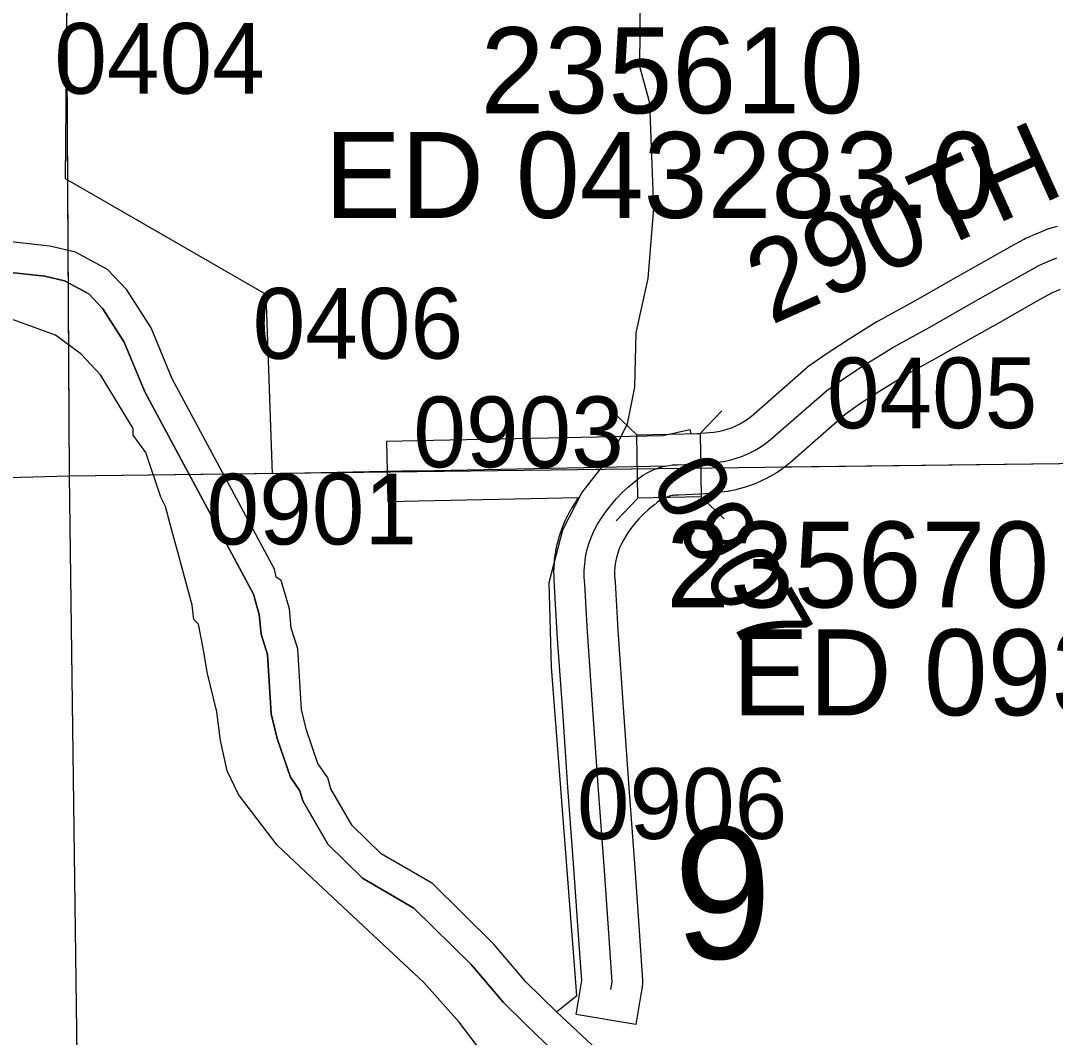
# Model space of a CAD drawing. Extents: x 23.6 to 68.7, y -63 to -29.
# Drawn here: x 40.707 to 41.731, y -53.223 to -52.217 of the extents above; entities that cross this region are included whole.
import ezdxf

# ---------------------------------------------------------------- set-up
doc = ezdxf.new("R2010")
doc.units = 0
for name, color, linetype in [('tdCoHydroRiver', 7, 'Continuous'), ('tdCoSecRdNmbr', 7, 'Continuous'), ('tdCoSecRdTxt', 7, 'Continuous'), ('tdCoSecRteBand', 7, 'Continuous'), ('tdCoSecRteCL', 7, 'Continuous'), ('tdCoSectLine', 7, 'Continuous'), ('tdCoSectLinePart', 7, 'Continuous'), ('tdCoSectNmbr', 7, 'Continuous'), ('tdCoStrucSec', 7, 'Continuous'), ('tdCoStrucSecCoName', 7, 'Continuous'), ('tdCoStrucSecFHWANum', 7, 'Continuous'), ('tdCoSurfEarth', 7, 'Continuous'), ('tdCoSurfGravel', 7, 'Continuous'), ('tdCoSurfLNO', 7, 'Continuous'), ('tdCoTwpBndry', 7, 'Continuous'), ('tdCoTwpBndryShd', 7, 'Continuous')]:
    doc.layers.add(name, color=color, linetype=linetype)

msp = doc.modelspace()

# ---------------------------------------------------------------- linework, layer by layer
at = {"layer": 'tdCoHydroRiver'}
for points in [[(41.2371, -53.1973), (41.2575, -53.1813), (41.2323, -52.8564), (41.2299, -52.7727), (41.2436, -52.7205), (41.2622, -52.684), (41.2919, -52.6458), (41.3074, -52.6157), (41.3149, -52.5793), (41.316, -52.5256), (41.3281, -52.4718), (41.3337, -52.4023), (41.3296, -52.2982), (41.3198, -52.262), (41.3222, -52.0157)], [(41.2371, -53.1973), (41.2068, -53.1676), (41.1749, -53.13), (41.1144, -53.0706), (41.0636, -53.0411), (41.0349, -53.0129), (41.014, -52.9768), (41.0108, -52.9658), (41.0011, -52.9517), (40.9898, -52.9186), (40.9849, -52.8982), (40.9811, -52.8382), (40.9746, -52.8178), (40.9729, -52.7988), (40.9647, -52.7705), (40.9599, -52.7674), (40.9583, -52.7595), (40.857, -52.571), (40.836, -52.5207), (40.812, -52.4831), (40.7929, -52.4627), (40.7611, -52.4457), (40.7358, -52.4396), (40.6821, -52.4338)], [(41.1921, -53.2751), (41.1409, -53.2077), (41.1058, -53.1685), (41.0007, -53.0701), (40.9609, -53.0326), (40.9225, -52.9824), (40.9112, -52.9589), (40.9046, -52.9289), (40.9012, -52.9005), (40.8914, -52.8612), (40.888, -52.8391), (40.883, -52.8139), (40.8782, -52.8092), (40.8765, -52.795), (40.8634, -52.7462), (40.8553, -52.7163), (40.8504, -52.6974), (40.8455, -52.688), (40.8309, -52.6439), (40.8181, -52.6267), (40.8181, -52.6203), (40.786, -52.567), (40.7668, -52.5466), (40.7414, -52.5279), (40.6907, -52.5095)], [(41.7341, -53.6693), (41.7276, -53.6551), (41.7117, -53.6427), (41.6468, -53.6149), (41.5896, -53.5807), (41.5466, -53.5385), (41.5481, -53.5306), (41.5322, -53.5165), (41.505, -53.4836), (41.4812, -53.4649), (41.462, -53.4382), (41.4284, -53.3944), (41.3072, -53.2629), (41.2371, -53.1973)]]:
    msp.add_lwpolyline(points, dxfattribs=at)
at = {"layer": 'tdCoSecRteBand'}
msp.add_lwpolyline([(41.7356, -52.4826), (41.7277, -52.486), (41.7156, -52.4926), (41.669, -52.5191), (41.6689, -52.5191), (41.6689, -52.5191), (41.6213, -52.546), (41.6212, -52.5461), (41.621, -52.5462), (41.5855, -52.5658), (41.5563, -52.584), (41.5383, -52.5956), (41.5231, -52.6064), (41.469, -52.6537), (41.4683, -52.6543), (41.4677, -52.6548), (41.4625, -52.6588), (41.4617, -52.6594), (41.4609, -52.66), (41.4555, -52.6636), (41.4547, -52.6642), (41.4539, -52.6647), (41.4482, -52.668), (41.4474, -52.6685), (41.4465, -52.6689), (41.4407, -52.6718), (41.4398, -52.6723), (41.4389, -52.6727), (41.4329, -52.6752), (41.432, -52.6756), (41.431, -52.6759), (41.4249, -52.678), (41.4239, -52.6783), (41.423, -52.6786), (41.4167, -52.6803), (41.4158, -52.6806), (41.4148, -52.6808), (41.4084, -52.6821), (41.4074, -52.6823), (41.4065, -52.6824), (41.4, -52.6833), (41.3994, -52.6834), (41.3989, -52.6834), (41.3811, -52.6852), (41.3802, -52.6852), (41.3792, -52.6853), (41.3581, -52.686), (41.3545, -52.6862), (41.353, -52.6864), (41.3518, -52.6866), (41.3491, -52.6872), (41.3464, -52.688), (41.3439, -52.689), (41.3414, -52.6903), (41.339, -52.6917), (41.3368, -52.6933), (41.3338, -52.6959), (41.3336, -52.696), (41.3335, -52.6962), (41.328, -52.7007), (41.3233, -52.705), (41.3189, -52.7096), (41.3147, -52.7143), (41.3108, -52.7193), (41.3072, -52.7245), (41.3039, -52.7299), (41.3011, -52.735), (41.2994, -52.739), (41.2979, -52.7434), (41.2966, -52.7479), (41.2957, -52.7524), (41.295, -52.757), (41.2947, -52.7617), (41.2948, -52.7663), (41.2952, -52.772), (41.2952, -52.7722), (41.2952, -52.7724), (41.2979, -52.8196), (41.3036, -52.9008), (41.3085, -52.9713), (41.3147, -53.0553), (41.3147, -53.0554), (41.3147, -53.0554), (41.3193, -53.122), (41.3193, -53.122), (41.3193, -53.1221), (41.3223, -53.166), (41.3225, -53.1695), (41.322, -53.1729), (41.3207, -53.1803), (41.3158, -53.2099), (41.2566, -53.2), (41.2616, -53.1705), (41.2622, -53.1665), (41.2595, -53.1262), (41.2548, -53.0597), (41.2486, -52.9756), (41.2486, -52.9756), (41.2486, -52.9755), (41.2437, -52.905), (41.2437, -52.905), (41.2437, -52.905), (41.238, -52.8236), (41.238, -52.8234), (41.238, -52.8232), (41.2353, -52.7761), (41.2348, -52.7696), (41.2348, -52.7686), (41.2348, -52.7676), (41.2347, -52.7609), (41.2347, -52.7598), (41.2348, -52.7588), (41.2352, -52.7521), (41.2353, -52.7511), (41.2354, -52.7501), (41.2363, -52.7434), (41.2365, -52.7424), (41.2367, -52.7414), (41.238, -52.7348), (41.2382, -52.7338), (41.2385, -52.7328), (41.2403, -52.7263), (41.2406, -52.7253), (41.2409, -52.7244), (41.2432, -52.718), (41.2435, -52.7171), (41.2439, -52.7161), (41.2466, -52.71), (41.2471, -52.7087), (41.2478, -52.7075), (41.2516, -52.7005), (41.252, -52.6998), (41.2524, -52.6991), (41.2566, -52.6923), (41.257, -52.6917), (41.2575, -52.691), (41.259, -52.6889), (41.1006, -52.6921), (41.0706, -52.6927), (41.0694, -52.6327), (41.0994, -52.6321), (41.3428, -52.6271), (41.3692, -52.6212), (41.3701, -52.6256), (41.3762, -52.6253), (41.3925, -52.6238), (41.3974, -52.6231), (41.4018, -52.6222), (41.4062, -52.621), (41.4105, -52.6195), (41.4147, -52.6177), (41.4187, -52.6157), (41.4227, -52.6134), (41.4264, -52.6109), (41.4301, -52.608), (41.4847, -52.5602), (41.4858, -52.5592), (41.4871, -52.5583), (41.5041, -52.5462), (41.5047, -52.5459), (41.5052, -52.5455), (41.524, -52.5334), (41.5242, -52.5333), (41.5244, -52.5332), (41.5544, -52.5144), (41.5551, -52.514), (41.5558, -52.5136), (41.5919, -52.4937), (41.6394, -52.4669), (41.6862, -52.4403), (41.6864, -52.4402), (41.6866, -52.4401), (41.7002, -52.4327), (41.7014, -52.432), (41.7027, -52.4315), (41.7118, -52.4275), (41.7118, -52.4275), (41.7119, -52.4275), (41.7205, -52.4238), (41.7225, -52.4229), (41.7246, -52.4223), (41.733, -52.4201)], dxfattribs=at)
at = {"layer": 'tdCoSecRteCL'}
msp.add_line((41.1, -52.6621), (41.3464, -52.6571), dxfattribs=at)
for points in [[(41.3464, -52.6571), (41.3489, -52.6567), (41.3516, -52.6563), (41.3567, -52.656), (41.3782, -52.6553), (41.396, -52.6536), (41.4024, -52.6527), (41.4088, -52.6514), (41.4151, -52.6497), (41.4212, -52.6475), (41.4272, -52.645), (41.4331, -52.6421), (41.4387, -52.6388), (41.4441, -52.6351), (41.4492, -52.6311), (41.5045, -52.5828), (41.5215, -52.5707), (41.5402, -52.5586), (41.5703, -52.5399), (41.6066, -52.5199), (41.6541, -52.493), (41.701, -52.4664), (41.7146, -52.459), (41.7237, -52.455), (41.7323, -52.4513)], [(41.2911, -53.1754), (41.2924, -53.168), (41.2894, -53.1241), (41.2847, -53.0575), (41.2786, -52.9734), (41.2736, -52.9029), (41.268, -52.8215), (41.2652, -52.7742), (41.2648, -52.7675), (41.2647, -52.7608), (41.2652, -52.7541), (41.2661, -52.7474), (41.2674, -52.7408), (41.2692, -52.7344), (41.2715, -52.728), (41.2741, -52.7219), (41.2779, -52.7149), (41.2821, -52.7081), (41.2867, -52.7016), (41.2916, -52.6953), (41.2968, -52.6893), (41.3023, -52.6835), (41.3082, -52.6781), (41.3143, -52.673), (41.3183, -52.6697), (41.3225, -52.6667), (41.3269, -52.664), (41.3316, -52.6617), (41.3364, -52.6597), (41.3414, -52.6582), (41.3464, -52.6571)]]:
    msp.add_lwpolyline(points, dxfattribs=at)
at = {"layer": 'tdCoSectLine'}
for points in [[(40.7489, -51.6298), (40.7549, -52.667)], [(40.7549, -52.667), (41.7618, -52.6544)], [(39.7494, -52.6946), (40.7549, -52.667)], [(40.7549, -52.667), (40.7682, -53.6656)]]:
    msp.add_lwpolyline(points, dxfattribs=at)
at = {"layer": 'tdCoSectLinePart'}
for points in [[(40.7516, -52.1015), (40.7549, -52.667)], [(41.4623, -52.6581), (41.7618, -52.6544)], [(40.7549, -52.667), (41.0687, -52.6631)], [(39.7795, -52.6937), (40.7549, -52.667)], [(40.7549, -52.667), (40.7642, -53.3662)]]:
    msp.add_lwpolyline(points, dxfattribs=at)
at = {"layer": 'tdCoStrucSec'}
for p, q in [((41.3793, -52.6253), (41.401, -52.6027)), ((41.3167, -52.6265), (41.2941, -52.6048)), ((41.3179, -52.6891), (41.2962, -52.7117)), ((41.3805, -52.6879), (41.4031, -52.7096))]:
    msp.add_line(p, q, dxfattribs=at)
msp.add_lwpolyline([(41.3167, -52.6265), (41.3793, -52.6253), (41.3805, -52.6879), (41.3179, -52.6891)], close=True, dxfattribs=at)
at = {"layer": 'tdCoSurfEarth'}
msp.add_lwpolyline([(41.1, -52.6621), (41.3464, -52.6571), (41.3489, -52.6567)], dxfattribs=at)
at = {"layer": 'tdCoSurfGravel'}
for points in [[(41.3489, -52.6567), (41.3516, -52.6563), (41.3567, -52.656), (41.3782, -52.6553), (41.396, -52.6536), (41.4024, -52.6527), (41.4088, -52.6514), (41.4151, -52.6497), (41.4212, -52.6475), (41.4272, -52.645), (41.4331, -52.6421), (41.4387, -52.6388), (41.4441, -52.6351), (41.4492, -52.6311), (41.5045, -52.5828), (41.5215, -52.5707), (41.5402, -52.5586), (41.5703, -52.5399), (41.6066, -52.5199), (41.6541, -52.493), (41.701, -52.4664), (41.7146, -52.459), (41.7237, -52.455), (41.7323, -52.4513)], [(41.2911, -53.1754), (41.2924, -53.168), (41.2894, -53.1241), (41.2847, -53.0575), (41.2786, -52.9734), (41.2736, -52.9029), (41.268, -52.8215), (41.2652, -52.7742), (41.2648, -52.7675), (41.2647, -52.7608), (41.2652, -52.7541), (41.2661, -52.7474), (41.2674, -52.7408), (41.2692, -52.7344), (41.2715, -52.728), (41.2741, -52.7219), (41.2779, -52.7149), (41.2821, -52.7081), (41.2867, -52.7016), (41.2916, -52.6953), (41.2968, -52.6893), (41.3023, -52.6835), (41.3082, -52.6781), (41.3143, -52.673), (41.3183, -52.6697), (41.3225, -52.6667), (41.3269, -52.664), (41.3316, -52.6617), (41.3364, -52.6597), (41.3414, -52.6582), (41.3464, -52.6571)]]:
    msp.add_lwpolyline(points, dxfattribs=at)
at = {"layer": 'tdCoSurfLNO'}
for p, q in [((40.7513, -52.3731), (40.754, -52.0708)), ((40.9499, -52.4876), (40.7513, -52.3731)), ((40.9562, -52.6651), (40.9499, -52.4876)), ((41.0999, -52.6621), (40.9562, -52.6651))]:
    msp.add_line(p, q, dxfattribs=at)
at = {"layer": 'tdCoTwpBndry'}
for points in [[(41.2162, -53.219), (41.2065, -53.2095), (41.1847, -53.1881), (41.1528, -53.1505), (41.0959, -53.0947), (41.0452, -53.0652), (41.0108, -53.0316), (40.9861, -52.9888), (40.9832, -52.9789), (40.974, -52.9653), (40.9608, -52.9271), (40.9549, -52.9027), (40.9513, -52.8438), (40.9449, -52.8238), (40.9431, -52.8044), (40.9372, -52.784), (40.8298, -52.584), (40.8092, -52.5347), (40.7881, -52.5017), (40.7743, -52.4869), (40.7503, -52.4741), (40.7307, -52.4693), (40.6818, -52.4641)], [(41.7366, -53.7177), (41.7085, -53.6859), (41.7033, -53.6743), (41.6962, -53.6688), (41.633, -53.6418), (41.5711, -53.6047), (41.514, -53.5487), (41.5153, -53.5418), (41.5104, -53.5375), (41.4839, -53.5053), (41.4592, -53.486), (41.4378, -53.4562), (41.4053, -53.4138), (41.2858, -53.2842), (41.2255, -53.2277), (41.2162, -53.219)]]:
    msp.add_lwpolyline(points, dxfattribs=at)
at = {"layer": 'tdCoTwpBndryShd'}
msp.add_lwpolyline([(40.6818, -52.4641), (40.7307, -52.4693), (40.7503, -52.4741), (40.7743, -52.4869), (40.7881, -52.5017), (40.8092, -52.5347), (40.8298, -52.584), (40.9372, -52.784), (40.9431, -52.8044), (40.9449, -52.8238), (40.9513, -52.8438), (40.9549, -52.9027), (40.9608, -52.9271), (40.974, -52.9653), (40.9832, -52.9789), (40.9861, -52.9888), (41.0108, -53.0316), (41.0452, -53.0652), (41.0959, -53.0947), (41.1528, -53.1505), (41.1847, -53.1881), (41.2065, -53.2095), (41.2162, -53.219), (41.2255, -53.2277)], dxfattribs=at)

# ---------------------------------------------------------------- texts
at = {"layer": 'tdCoSecRdNmbr'}
for s, rotation, p in [('0404', 0.0319, (40.7403, -52.289)), ('0406', 0.0321, (40.9366, -52.5512)), ('0405', 0.0325, (41.5049, -52.62)), ('0903', 0.0321, (41.0956, -52.6586)), ('0907', 300.0314, (41.3287, -52.6724)), ('0901', 0.0301, (40.8909, -52.735)), ('0906', 0.0323, (41.2574, -53.0264))]:
    msp.add_text(s, height=0.07, rotation=rotation, dxfattribs=at).set_placement(p)
at = {"layer": 'tdCoSecRdTxt'}
msp.add_text('290TH ST', height=0.08, rotation=24.1171, dxfattribs=at).set_placement((41.4495, -52.5182))
at = {"layer": 'tdCoSectNmbr'}
msp.add_text('9', height=0.13, rotation=1.0323, dxfattribs=at).set_placement((41.3547, -53.1456))
at = {"layer": 'tdCoStrucSecCoName'}
for s, p in [('ED 043283.0', (41.0076, -52.4118)), ('ED 093325.0', (41.4112, -52.904))]:
    msp.add_text(s, height=0.085, dxfattribs=at).set_placement(p)
at = {"layer": 'tdCoStrucSecFHWANum'}
for s, p in [('235610', (41.1622, -52.3082)), ('235670', (41.3457, -52.7973))]:
    msp.add_text(s, height=0.085, dxfattribs=at).set_placement(p)

doc.saveas('drawing.dxf')
